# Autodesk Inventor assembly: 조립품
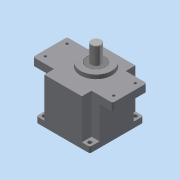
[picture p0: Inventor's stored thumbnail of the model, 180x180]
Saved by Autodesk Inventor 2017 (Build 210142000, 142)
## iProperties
Part Number: 조립품
Material: 일반
Document SubType Name: Assembly
Designer: user
Author: user
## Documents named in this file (10)
- C:\Users\user\Desktop\700116V1001\조립품.iam
- C:\Users\user\Desktop\700116V1001\메인 축.ipt
- C:\Users\user\Desktop\700116V1001\베어링 608.ipt
- C:\Users\user\Desktop\700116V1001\베어링 6003.ipt
- C:\Users\user\Desktop\700116V1001\본체.ipt
- C:\Users\user\Desktop\700116V1001\볼트 M4.ipt
- C:\Users\user\Desktop\700116V1001\서브 축.ipt
- C:\Users\user\Desktop\700116V1001\오일 실 8 22 7.ipt
- C:\Users\user\Desktop\700116V1001\오일 실 17 32 8.ipt
- C:\Users\user\Desktop\700116V1001\커버.ipt
